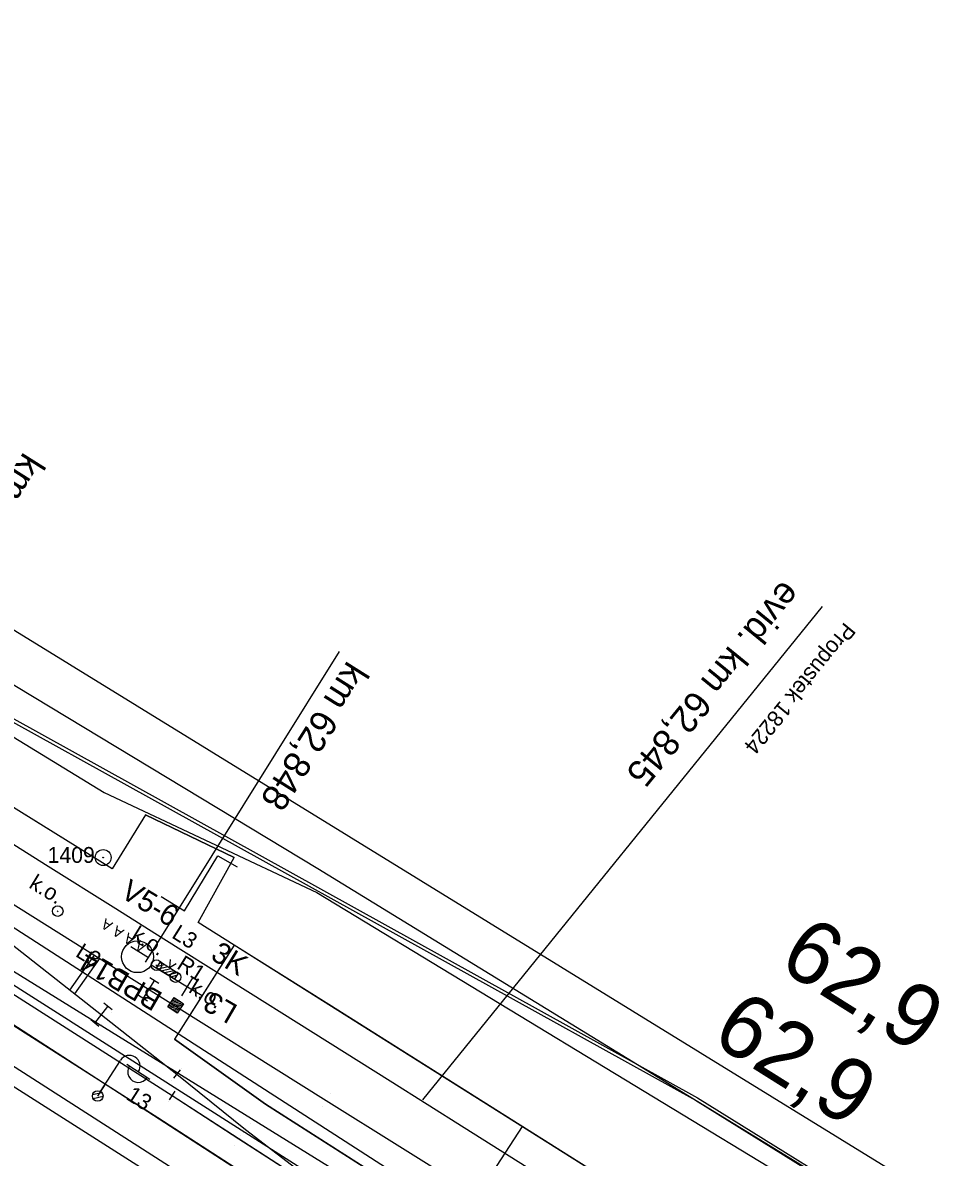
# Model space of a CAD drawing. Extents: x -621168 to -620292, y -1122748 to -1122069.
# Drawn here: x -620776.3 to -620688.9, y -1122403.6 to -1122296.3 of the extents above; entities that cross this region are included whole.
import ezdxf

# ---------------------------------------------------------------- set-up
doc = ezdxf.new("R2010")
doc.units = 0
for name, color, linetype in [('060601_EOV', 7, 'Continuous'), ('060604_ROZVODY_SEE', 7, 'Continuous'), ('CETIN', 7, 'Continuous'), ('HranDP', 7, 'Continuous'), ('Hranice parcel', 7, 'Continuous'), ('PS 06-14-01_trasa_sdělovací_nové', 7, 'Continuous'), ('SEE', 7, 'Continuous'), ('SSZT', 7, 'Continuous'), ('SSZT-DK', 7, 'Continuous'), ('UZEMNĚNÍ', 7, 'Continuous'), ('Vnitřní kresba', 7, 'Continuous'), ('Vrstva 1', 7, 'Continuous'), ('Vrstva 19', 7, 'Continuous'), ('Vrstva 2', 7, 'Continuous'), ('Vrstva 25', 7, 'Continuous'), ('Vrstva 27', 7, 'Continuous'), ('Vrstva 3', 7, 'Continuous'), ('Vrstva 36', 7, 'Continuous'), ('Vrstva 6', 7, 'Continuous'), ('Vrstva 62', 7, 'Continuous'), ('Vrstva 7', 7, 'Continuous'), ('Značky bodu BP', 7, 'Continuous'), ('ČD-T', 7, 'Continuous')]:
    doc.layers.add(name, color=color, linetype=linetype)

msp = doc.modelspace()

# ---------------------------------------------------------------- linework, layer by layer
at = {"layer": '060601_EOV'}
msp.add_lwpolyline([(-620377.18, -1122637.26), (-620411.56, -1122614.92), (-620424.16, -1122607.09), (-620443.53, -1122595), (-620456.11, -1122587.12), (-620447.82, -1122572.96), (-620450.95, -1122571.45), (-620470.59, -1122561.48), (-620499.61, -1122545.57), (-620522.04, -1122531.47), (-620538.89, -1122521.21), (-620599.21, -1122483.22), (-620683.52, -1122429.44), (-620729.12, -1122400.66), (-620738.89, -1122415.69), (-620750.53, -1122408.25), (-620763.56, -1122399.82), (-620784.65, -1122386.39), (-620822.22, -1122362.42), (-620817.53, -1122355.08), (-620826.41, -1122348.08), (-620839.92, -1122337.94), (-620848.84, -1122332), (-620848.83, -1122331.99)], dxfattribs=at)
at = {"layer": '060604_ROZVODY_SEE'}
msp.add_line((-620769.23, -1122397.79), (-620768.51, -1122396.66), dxfattribs=at)
msp.add_lwpolyline([(-620443.53, -1122595), (-620456.11, -1122587.12), (-620447.82, -1122572.96), (-620450.95, -1122571.45), (-620470.59, -1122561.48), (-620499.61, -1122545.57), (-620522.04, -1122531.47), (-620538.89, -1122521.21), (-620599.21, -1122483.22), (-620683.52, -1122429.44), (-620729.12, -1122400.66), (-620738.89, -1122415.69), (-620750.53, -1122408.25), (-620763.56, -1122399.82), (-620784.65, -1122386.39), (-620822.22, -1122362.42), (-620817.53, -1122355.08), (-620826.41, -1122348.08), (-620839.92, -1122337.94), (-620854.57, -1122328.18), (-620868.06, -1122319.69), (-620885.37, -1122308.82), (-620912.87, -1122291.53), (-620913.33, -1122292.25)], dxfattribs=at)
at = {"layer": 'CETIN'}
msp.add_lwpolyline([(-621086.89, -1122186.72), (-621044.7, -1122204.84), (-620975.94, -1122239.69), (-620943.1, -1122258.62), (-620748.44, -1122376.27), (-620484.52, -1122538.15)], dxfattribs=at)
at = {"layer": 'HranDP'}
for points in [[(-620847.72, -1122320.67), (-620838.83, -1122326.12), (-620768.63, -1122369.09), (-620748.53, -1122378.52), (-620702.13, -1122406.7), (-620691.02, -1122413.66), (-620638.48, -1122446.57), (-620552.09, -1122499.2)], [(-620821.12, -1122358.76), (-620741.46, -1122408.09), (-620679.51, -1122447.56), (-620545.92, -1122532.26), (-620521.41, -1122548.27), (-620511.29, -1122557.64)]]:
    msp.add_lwpolyline(points, dxfattribs=at)
at = {"layer": 'Hranice parcel'}
msp.add_line((-620866.03, -1122298.98), (-620688.16, -1122408.5), dxfattribs=at)
for points in [[(-620847.72, -1122320.67), (-620838.83, -1122326.12), (-620768.63, -1122369.09), (-620748.53, -1122378.52), (-620702.13, -1122406.7), (-620691.02, -1122413.66), (-620638.48, -1122446.57), (-620552.09, -1122499.2)], [(-620821.12, -1122358.76), (-620741.46, -1122408.09), (-620679.51, -1122447.56), (-620545.92, -1122532.26), (-620521.41, -1122548.27), (-620511.29, -1122557.64)], [(-620821.12, -1122358.76), (-620807.67, -1122367.84), (-620645.72, -1122471.03), (-620587.17, -1122509.18), (-620511.29, -1122557.64)], [(-620557.45, -1122536.96), (-620684.91, -1122455.63), (-620825.92, -1122365.89)]]:
    msp.add_lwpolyline(points, dxfattribs=at)
at = {"layer": 'PS 06-14-01_trasa_sdělovací_nové'}
for points in [[(-620756.33, -1122383.52), (-620759.75, -1122381.36), (-620756.35, -1122375.21), (-620764.72, -1122371.2), (-620767.85, -1122376.3), (-620853.07, -1122323.34), (-620895.69, -1122296.63), (-620912.11, -1122286.23), (-620914.88, -1122290.62), (-620964.54, -1122259.53), (-620982.11, -1122249.22), (-620983.24, -1122251.5), (-621017.63, -1122231.73), (-621052.34, -1122216.08), (-621085.52, -1122202.49), (-621084.03, -1122198.76), (-621092.03, -1122195.56)], [(-620538.89, -1122521.21), (-620538.89, -1122521.21), (-620599.21, -1122483.22), (-620683.52, -1122429.44), (-620756.33, -1122383.52), (-620761.98, -1122392.4), (-620753.37, -1122398.54), (-620735.26, -1122410.11), (-620735.26, -1122410.11)]]:
    msp.add_lwpolyline(points, dxfattribs=at)
at = {"layer": 'SEE'}
msp.add_lwpolyline([(-620377.19, -1122637.27), (-620390.25, -1122629.02), (-620411.93, -1122614.96), (-620423.13, -1122608.01), (-620468.34, -1122579.91), (-620468.34, -1122579.91), (-620460.94, -1122568.1), (-620517.42, -1122533.03), (-620535, -1122522.48), (-620545.41, -1122539.45), (-620611.37, -1122497.7), (-620665.57, -1122462.75), (-620686.03, -1122449.83), (-620727.54, -1122423.18), (-620794.51, -1122379.86), (-620815.52, -1122356.95), (-620832.17, -1122344.66), (-620847.81, -1122332.59), (-620908.26, -1122294.69)], dxfattribs=at)
at = {"layer": 'SSZT'}
for points in [[(-620879.24, -1122313.32), (-620842.99, -1122336.61), (-620835.05, -1122343.25), (-620812.66, -1122358.95), (-620764.9, -1122389.75), (-620688.59, -1122438.97), (-620596.98, -1122496.73), (-620576.74, -1122509.48), (-620506.75, -1122556.12), (-620447.29, -1122593.62), (-620377.76, -1122638.26)], [(-620763.25, -1122378.91), (-620761.03, -1122380.27), (-620757.87, -1122375.08), (-620756.04, -1122376.12)], [(-620763.25, -1122378.91), (-620761.03, -1122380.27), (-620757.87, -1122375.08), (-620756.04, -1122376.12)]]:
    msp.add_lwpolyline(points, dxfattribs=at)
at = {"layer": 'SSZT-DK'}
msp.add_lwpolyline([(-621084.33, -1122182.33), (-621080.25, -1122184.04), (-621051.5, -1122198.93), (-620999.37, -1122227), (-620959.93, -1122250.54), (-620931.35, -1122267.52), (-620900.27, -1122286.47), (-620889.15, -1122293.45), (-620783.74, -1122358.82), (-620712.75, -1122398.18), (-620653.12, -1122435.23), (-620617.36, -1122456.74), (-620574.42, -1122482.6), (-620528.16, -1122511.11), (-620496.31, -1122530.83), (-620515.02, -1122558.81), (-620500.38, -1122568.61), (-620465.39, -1122591.45), (-620452.16, -1122605.02), (-620438.23, -1122615.5), (-620392.31, -1122655.21), (-620389.25, -1122658.02)], dxfattribs=at)
at = {"layer": 'UZEMNĚNÍ'}
msp.add_line((-620769.23, -1122397.79), (-620768.51, -1122396.66), dxfattribs=at)
msp.add_lwpolyline([(-620742.35, -1122414.85), (-620741.73, -1122413.88), (-620750.53, -1122408.25), (-620763.56, -1122399.82), (-620784.65, -1122386.39), (-620822.22, -1122362.42), (-620817.53, -1122355.08), (-620826.41, -1122348.08), (-620838.67, -1122338.88), (-620840.23, -1122340.95)], dxfattribs=at)
at = {"layer": 'Vnitřní kresba'}
msp.add_line((-620810.36, -1122373.73), (-620648.08, -1122477.56), dxfattribs=at)
at = {"layer": 'Vrstva 1'}
for p, q in [((-620764.72, -1122371.2), (-620756.35, -1122375.21)), ((-620756.33, -1122383.52), (-620759.35, -1122388.27)), ((-620760.76, -1122387.45), (-620759.35, -1122388.27)), ((-620759.35, -1122388.27), (-620761.98, -1122392.4))]:
    msp.add_line(p, q, dxfattribs=at)
for points in [[(-620851.64, -1122327.08), (-620843.14, -1122332.43), (-620837.63, -1122335.92), (-620832.12, -1122339.39), (-620828.02, -1122341.97), (-620823.79, -1122344.63), (-620816.97, -1122348.94), (-620810.35, -1122353.09), (-620803.86, -1122357.18), (-620803.36, -1122357.5), (-620800.13, -1122359.53), (-620798.65, -1122360.46), (-620794.42, -1122363.12), (-620788.1, -1122367.1), (-620781.12, -1122371.5), (-620774.17, -1122375.88), (-620767.51, -1122380.06), (-620763.22, -1122382.76), (-620756.39, -1122387.05), (-620748.87, -1122391.78), (-620741.59, -1122396.35), (-620734.61, -1122400.75), (-620727.79, -1122405.03)], [(-620851.64, -1122327.08), (-620840.38, -1122334.59), (-620831.19, -1122341.26), (-620824.9, -1122346.12), (-620811.35, -1122356.78), (-620800.85, -1122364.55), (-620800.09, -1122365.07), (-620796.17, -1122367.69), (-620795.02, -1122368.44), (-620786.31, -1122373.93), (-620764.42, -1122387.67), (-620747.63, -1122398.19), (-620733.73, -1122406.89), (-620718.35, -1122416.52), (-620703.01, -1122426.15), (-620686.98, -1122436.2), (-620670.85, -1122446.34), (-620652.24, -1122458.03), (-620632.99, -1122470.12), (-620616.99, -1122480.17), (-620599.71, -1122491.04), (-620582.33, -1122501.97), (-620566.97, -1122511.73)], [(-620811.35, -1122356.78), (-620801.08, -1122364.82), (-620794.03, -1122370.35), (-620788.08, -1122375), (-620768.88, -1122390.1), (-620768.43, -1122390.45), (-620761.75, -1122395.7), (-620755.25, -1122400.95), (-620748.86, -1122405.85), (-620748.16, -1122406.32), (-620737.32, -1122413.73), (-620723.13, -1122422.77)], [(-620764.72, -1122371.2), (-620767.85, -1122376.3), (-620794.6, -1122359.68), (-620795.27, -1122359.26)], [(-620807.15, -1122369.06), (-620804.38, -1122370.84), (-620783.31, -1122384.28), (-620762.21, -1122397.72), (-620749.18, -1122406.14), (-620748.33, -1122406.68), (-620737.32, -1122413.73)], [(-620781.12, -1122371.5), (-620774.17, -1122375.88), (-620767.51, -1122380.06), (-620763.22, -1122382.76), (-620756.39, -1122387.05), (-620748.87, -1122391.78), (-620741.59, -1122396.35), (-620734.61, -1122400.75), (-620727.79, -1122405.03)], [(-620756.33, -1122383.52), (-620759.75, -1122381.36), (-620756.35, -1122375.21)], [(-620538.89, -1122521.21), (-620599.21, -1122483.22), (-620683.52, -1122429.44), (-620747.38, -1122389.13), (-620756.33, -1122383.52)], [(-620738.73, -1122407.89), (-620753.37, -1122398.54), (-620761.98, -1122392.4)]]:
    msp.add_lwpolyline(points, dxfattribs=at)
at = {"layer": 'Vrstva 19'}
msp.add_line((-620700.78, -1122351.5), (-620738.53, -1122398.14), dxfattribs=at)
at = {"layer": 'Vrstva 2'}
for p, q in [((-620764.19, -1122385.38), (-620760.76, -1122387.45)), ((-620761.28, -1122388.31), (-620760.25, -1122386.59)), ((-620761.23, -1122388.99), (-620762.52, -1122389.24)), ((-620761.39, -1122388.88), (-620762.42, -1122389.09)), ((-620761.54, -1122388.78), (-620762.31, -1122388.93)), ((-620761.7, -1122388.68), (-620762.21, -1122388.78)), ((-620761.85, -1122388.57), (-620762.11, -1122388.63)), ((-620761.17, -1122389.11), (-620762.54, -1122389.38)), ((-620761.27, -1122389.26), (-620762.38, -1122389.48)), ((-620761.37, -1122389.42), (-620762.23, -1122389.59)), ((-620761.48, -1122389.57), (-620762.07, -1122389.69)), ((-620761.58, -1122389.72), (-620761.92, -1122389.79)), ((-620761.68, -1122389.88), (-620761.76, -1122389.9)), ((-620761.44, -1122395.31), (-620762.07, -1122396.09)), ((-620761.94, -1122397.3), (-620762.48, -1122398.14))]:
    msp.add_line(p, q, dxfattribs=at)
msp.add_lwpolyline([(-620761.72, -1122389.93), (-620762.59, -1122389.35), (-620762.01, -1122388.47), (-620761.13, -1122389.06)], close=True, dxfattribs=at)
msp.add_lwpolyline([(-620761.72, -1122389.93), (-620762.59, -1122389.35), (-620762.01, -1122388.47), (-620761.13, -1122389.06)], close=True, dxfattribs=at)
for points in [[(-620761.75, -1122395.7), (-620755.25, -1122400.95), (-620748.86, -1122405.85), (-620748.16, -1122406.32), (-620737.32, -1122413.73)], [(-620762.21, -1122397.72), (-620755.9, -1122401.82), (-620749.18, -1122406.14), (-620748.33, -1122406.68), (-620737.32, -1122413.73)]]:
    msp.add_lwpolyline(points, dxfattribs=at)
msp.add_circle((-620765.47, -1122384.61), 1.5, dxfattribs=at)
at = {"layer": 'Vrstva 25'}
for p, q in [((-620768.96, -1122397.35), (-620767.08, -1122394.4)), ((-620766.49, -1122394.77), (-620764.29, -1122396.17)), ((-620769.71, -1122397.64), (-620768.85, -1122397.45)), ((-620769.66, -1122398.01), (-620768.73, -1122397.8))]:
    msp.add_line(p, q, dxfattribs=at)
msp.add_circle((-620769.23, -1122397.77), 0.5, dxfattribs=at)
for centre, start, end in [((-620766.23, -1122394.93), 327.5056, 147.5056), ((-620765.4, -1122395.48), 146.803, 328.2082)]:
    msp.add_arc(centre, 1, start, end, dxfattribs=at)
at = {"layer": 'Vrstva 27'}
for p, q in [((-620773.05, -1122380.26), (-620772.96, -1122380.32)), ((-620763.73, -1122385.37), (-620763.64, -1122385.42)), ((-620761.92, -1122386.5), (-620761.84, -1122386.56))]:
    msp.add_line(p, q, dxfattribs=at)
for centre in [(-620773.01, -1122380.29), (-620763.68, -1122385.4), (-620761.88, -1122386.53)]:
    msp.add_circle(centre, 0.5, dxfattribs=at)
at = {"layer": 'Vrstva 3'}
for p, q in [((-620763.88, -1122386.82), (-620764.95, -1122388.52)), ((-620764.31, -1122386.56), (-620763.46, -1122387.09)), ((-620767.87, -1122389.62), (-620768.66, -1122389)), ((-620765.37, -1122388.25), (-620764.52, -1122388.78)), ((-620769.5, -1122390.88), (-620768.26, -1122389.31)), ((-620769.11, -1122391.19), (-620769.89, -1122390.57))]:
    msp.add_line(p, q, dxfattribs=at)
at = {"layer": 'Vrstva 36'}
for p, q in [((-620763.56, -1122385.49), (-620762.91, -1122385.34)), ((-620763.53, -1122385.74), (-620762.61, -1122385.53)), ((-620763.37, -1122385.19), (-620763.21, -1122385.15)), ((-620763.23, -1122385.93), (-620762.31, -1122385.72)), ((-620762.93, -1122386.11), (-620762.01, -1122385.9)), ((-620762.63, -1122386.3), (-620761.71, -1122386.09)), ((-620762.33, -1122386.49), (-620761.74, -1122386.36)), ((-620762.03, -1122386.68), (-620761.93, -1122386.66))]:
    msp.add_line(p, q, dxfattribs=at)
msp.add_lwpolyline([(-620763.31, -1122385.09), (-620761.62, -1122386.15), (-620761.97, -1122386.72), (-620763.66, -1122385.65)], close=True, dxfattribs=at)
msp.add_lwpolyline([(-620762.39, -1122384.88), (-620762.46, -1122385.62), (-620761.83, -1122385.23)], dxfattribs=at)
at = {"layer": 'Vrstva 6'}
for p, q in [((-620764.44, -1122384.69), (-620746.39, -1122355.76)), ((-620766.11, -1122383.63), (-620764.44, -1122384.69)), ((-620766.11, -1122383.64), (-620764.44, -1122384.69)), ((-620764.7, -1122385.11), (-620764.17, -1122384.26)), ((-620764.7, -1122385.11), (-620764.17, -1122384.26))]:
    msp.add_line(p, q, dxfattribs=at)
at = {"layer": 'Vrstva 62'}
for p, q in [((-620764.05, -1122387.05), (-620764.05, -1122387.05)), ((-620764.78, -1122388.29), (-620764.78, -1122388.29)), ((-620768.4, -1122389.49), (-620768.4, -1122389.49)), ((-620767.95, -1122389.84), (-620767.95, -1122389.84)), ((-620769.29, -1122390.63), (-620769.29, -1122390.63)), ((-620768.85, -1122390.98), (-620768.85, -1122390.98)), ((-620761.29, -1122395.14), (-620761.29, -1122395.14)), ((-620762.22, -1122396.26), (-620762.22, -1122396.26)), ((-620761.84, -1122397.11), (-620761.84, -1122397.11)), ((-620747.24, -1122397.58), (-620747.24, -1122397.58)), ((-620762.57, -1122398.32), (-620762.57, -1122398.32)), ((-620748.02, -1122398.8), (-620748.02, -1122398.8)), ((-620754.81, -1122400.37), (-620754.81, -1122400.37)), ((-620755.7, -1122401.54), (-620755.7, -1122401.54)), ((-620755.49, -1122401.22), (-620755.49, -1122401.22)), ((-620756.31, -1122402.42), (-620756.31, -1122402.42))]:
    msp.add_line(p, q, dxfattribs=at)
at = {"layer": 'Vrstva 7'}
for p, q in [((-620771.87, -1122387.75), (-620769.54, -1122384.45)), ((-620771.39, -1122388.12), (-620769.03, -1122384.77)), ((-620770.46, -1122386.27), (-620770.46, -1122386.27))]:
    msp.add_line(p, q, dxfattribs=at)
at = {"layer": 'Značky bodu BP'}
for radius in [0.75, 0.03]:
    msp.add_circle((-620768.72, -1122375.23), radius, dxfattribs=at)
at = {"layer": 'ČD-T'}
msp.add_lwpolyline([(-621084.19, -1122182.07), (-621080.06, -1122183.8), (-621051.32, -1122198.69), (-620999.18, -1122226.77), (-620959.75, -1122250.31), (-620931.16, -1122267.28), (-620900.08, -1122286.23), (-620888.96, -1122293.22), (-620783.56, -1122358.58), (-620712.56, -1122397.94), (-620652.93, -1122435), (-620617.18, -1122456.5), (-620574.24, -1122482.37), (-620527.97, -1122510.87), (-620481.08, -1122540.08), (-620497, -1122565.38), (-620499.27, -1122568.98), (-620465.21, -1122591.22), (-620451.97, -1122604.79), (-620438.05, -1122615.26), (-620392.12, -1122654.98), (-620389.1, -1122657.76)], dxfattribs=at)

# ---------------------------------------------------------------- texts
at = {"layer": 'Vrstva 19'}
for s, height, p in [('evid. km 62,845', 2.5, (-620704.49, -1122348.9)), ('Propustek 18224', 1.5, (-620698.65, -1122352.9))]:
    msp.add_text(s, height=height, rotation=230.7597, dxfattribs=at).set_placement(p)
at = {"layer": 'Vrstva 25'}
msp.add_text('13', height=1.5, rotation=327.5056, dxfattribs=at).set_placement((-620766.63, -1122398.02))
at = {"layer": 'Vrstva 27'}
for s, height, p in [('k.o.', 1.5, (-620775.82, -1122378.02)), ('V5-6', 2, (-620767.2, -1122378.9)), ('k.o.', 1.5, (-620766.17, -1122382.9)), ('3K', 2, (-620758.67, -1122384.77)), ('k.o.', 1.5, (-620760.72, -1122387.91))]:
    msp.add_text(s, height=height, rotation=328.4879, dxfattribs=at).set_placement(p)
at = {"layer": 'Vrstva 3'}
for s, p in [('BPB14', (-620762.97, -1122388.1)), ('L3', (-620755.87, -1122389.29))]:
    msp.add_text(s, height=2, rotation=149.8236, dxfattribs=at).set_placement(p)
at = {"layer": 'Vrstva 36'}
msp.add_text('R1', height=1.5, rotation=327.9268, dxfattribs=at).set_placement((-620761.85, -1122385.66))
at = {"layer": 'Vrstva 6'}
for s, height, rotation, p in [('km 62,811', 2.5, 237.7824, (-620776.21, -1122336.8)), ('km 62,848', 2.5, 237.7824, (-620745.61, -1122356.52)), ('  A A A A ', 1, 147.7824, (-620763.9, -1122383.84)), ('L3', 1.5, 327.7824, (-620762.33, -1122382.75)), ('  A A ', 1, 147.8824, (-620763.9, -1122383.84)), ('L3', 1.5, 327.8824, (-620771.42, -1122384.51))]:
    msp.add_text(s, height=height, rotation=rotation, dxfattribs=at).set_placement(p)
at = {"layer": 'Vrstva 7'}
for rotation, p in [(327.8649, (-620705.08, -1122385.56)), (327.8519, (-620711.42, -1122392.58))]:
    msp.add_text('62,9', height=6, rotation=rotation, dxfattribs=at).set_placement(p)
at = {"layer": 'Značky bodu BP'}
msp.add_text('1409', height=1.5, dxfattribs=at).set_placement((-620773.97, -1122375.73))

doc.saveas('drawing.dxf')
